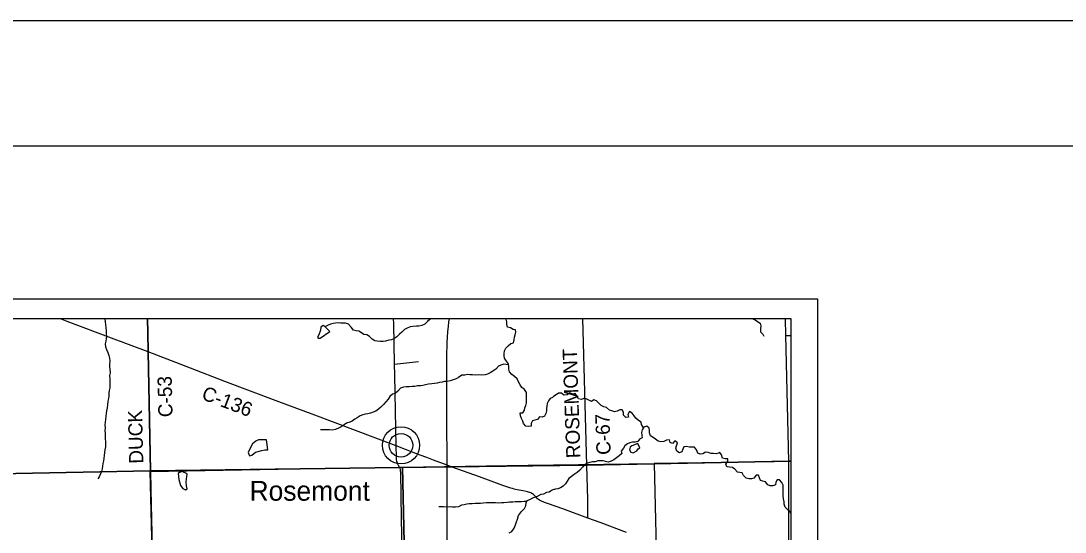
# Model space of a CAD drawing. Extents: x 0 to 34, y 0 to 22.
# Drawn here: x 6.707 to 10.885, y 19.953 to 22 of the extents above; entities that cross this region are included whole.
import ezdxf

# ---------------------------------------------------------------- set-up
doc = ezdxf.new("R2010")
doc.units = 0
for name, color, linetype in [('GM_X_Corporation', 7, 'Continuous'), ('GM_X_County_Road', 7, 'Continuous'), ('GM_X_County_Road_Text', 7, 'Continuous'), ('GM_X_Minor_Lake', 7, 'Continuous'), ('GM_X_Minor_River', 7, 'Continuous'), ('GM_X_Rail_Line', 7, 'Continuous'), ('GM_X_State_Route', 7, 'Continuous'), ('GM_X_Township_Road', 7, 'Continuous'), ('GM_X_Unincorporated', 7, 'Continuous'), ('GM_X_Unincorporated_Location', 7, 'Continuous'), ('GM_X_Unincorporated_Text', 7, 'Continuous'), ('SH_Border', 7, 'Continuous'), ('SH_Cut_Line', 7, 'Continuous'), ('SH_Data', 7, 'Continuous')]:
    doc.layers.add(name, color=color, linetype=linetype)

msp = doc.modelspace()

# ---------------------------------------------------------------- linework, layer by layer
at = {"layer": 'GM_X_Corporation'}
for points in [[(7.2136, 20.8069), (2.9895, 20.8069), (2.9895, 20.1176), (3.1549, 20.1187), (4.9925, 20.1548), (5.7004, 20.168), (6.0786, 20.1754), (7.2254, 20.198), (7.2157, 20.6753), (7.2146, 20.7526)], [(9.7895, 20.2375), (9.7895, 20.8069), (7.2136, 20.8069), (7.2146, 20.7526), (7.2157, 20.6753), (7.2254, 20.198), (8.2231, 20.2112), (8.4324, 20.2139), (8.9707, 20.221), (9.7789, 20.2374)], [(9.2406, 20.2272), (9.2644, 19.2076), (8.2571, 19.1893), (8.2335, 20.2135), (8.7368, 20.2215)], [(9.7895, 19.2182), (9.7895, 20.2353), (9.7215, 20.2341), (9.2406, 20.2272), (9.2644, 19.2076)], [(8.2335, 20.2135), (8.2571, 19.1893), (7.2437, 19.1696), (7.2401, 19.5595), (7.2243, 20.1958), (7.7364, 20.2052)]]:
    msp.add_lwpolyline(points, close=True, dxfattribs=at)
for points in [[(9.7895, 15.1275), (9.7895, 20.2375), (9.7789, 20.2374), (8.9707, 20.221), (8.4324, 20.2139), (8.2231, 20.2112), (7.2254, 20.198), (7.2266, 20.122), (7.2291, 20.0061), (7.2317, 19.8848), (7.2344, 19.7492), (7.237, 19.6097), (7.2392, 19.4543), (7.2426, 19.2998), (7.2468, 19.0896), (7.2467, 19.0557), (7.2751, 17.5764), (7.2764, 17.5202), (7.2799, 17.4174), (7.283, 17.3071), (7.2872, 17.1772)], [(7.2872, 17.1772), (7.283, 17.3071), (7.2799, 17.4174), (7.2764, 17.5202), (7.2751, 17.5764), (7.2467, 19.0557), (7.2468, 19.0896), (7.2426, 19.2998), (7.2392, 19.4543), (7.237, 19.6097), (7.2344, 19.7492), (7.2317, 19.8848), (7.2291, 20.0061), (7.2266, 20.122), (7.2254, 20.198), (6.0786, 20.1754), (5.7004, 20.168), (4.9925, 20.1548), (3.1549, 20.1187), (2.9895, 20.1176), (2.9895, 14.989)]]:
    msp.add_lwpolyline(points, dxfattribs=at)
at = {"layer": 'GM_X_County_Road'}
msp.add_line((9.7678, 20.7398), (9.7895, 20.7405), dxfattribs=at)
for points in [[(7.2159, 20.6747), (7.0699, 20.7296), (6.8916, 20.7969), (6.865, 20.8069)], [(7.2256, 20.1974), (7.2159, 20.6747), (7.2148, 20.7521), (7.2138, 20.8069)], [(8.2079, 20.2985), (8.2072, 20.3674), (8.2029, 20.5818), (8.202, 20.6251), (8.1986, 20.789), (8.1983, 20.8069)], [(8.9709, 20.2185), (8.9709, 20.2205), (8.9569, 20.7602), (8.9556, 20.8069)], [(8.2079, 20.2985), (7.8827, 20.4213), (7.7288, 20.4791), (7.5235, 20.5566), (7.3849, 20.6093), (7.2159, 20.6747)], [(8.2177, 20.2203), (8.2147, 20.2255), (8.2131, 20.2296), (8.2118, 20.2333), (8.2108, 20.2369), (8.21, 20.2424), (8.2095, 20.2475), (8.2093, 20.2532), (8.2079, 20.2985)], [(8.4121, 20.221), (8.3573, 20.2415), (8.3308, 20.2515), (8.3047, 20.2613), (8.2452, 20.2838), (8.2079, 20.2985)], [(7.2469, 19.0552), (7.247, 19.089), (7.2428, 19.2992), (7.2394, 19.4537), (7.2372, 19.6092), (7.2346, 19.7487), (7.2319, 19.8843), (7.2293, 20.0056), (7.2268, 20.1215), (7.2256, 20.1974)], [(8.2622, 18.3652), (8.2632, 18.4054), (8.2621, 18.4472), (8.2592, 18.5595), (8.2549, 18.7216), (8.2466, 19.0147), (8.2435, 19.1769), (8.2421, 19.255), (8.2402, 19.3805), (8.2379, 19.507), (8.2357, 19.6472), (8.2338, 19.785), (8.2321, 19.8769), (8.2296, 20.0073), (8.2268, 20.1925), (8.2264, 20.1978), (8.2261, 20.2017), (8.2255, 20.2048), (8.2246, 20.2076), (8.2233, 20.2106), (8.2177, 20.2203)], [(9.1303, 19.951), (9.0241, 19.991), (8.9758, 20.0091), (8.8759, 20.0468), (8.8178, 20.0667), (8.802, 20.0719), (8.7972, 20.0739), (8.7925, 20.0758), (8.7876, 20.0782), (8.7822, 20.0812), (8.7775, 20.0842), (8.7744, 20.087), (8.7697, 20.092), (8.765, 20.0968), (8.7607, 20.1009), (8.7577, 20.1036), (8.7542, 20.106), (8.7508, 20.108), (8.7472, 20.1098), (8.7432, 20.1112), (8.7386, 20.1128), (8.734, 20.1142), (8.7285, 20.1155), (8.7162, 20.1182), (8.693, 20.1224), (8.6855, 20.1241), (8.68, 20.1255), (8.6735, 20.1272), (8.6669, 20.1293), (8.6554, 20.1332), (8.6354, 20.1402), (8.5414, 20.174), (8.4326, 20.2134), (8.4121, 20.221)], [(8.9758, 20.0091), (8.9752, 20.0848), (8.9709, 20.2185)]]:
    msp.add_lwpolyline(points, dxfattribs=at)
at = {"layer": 'GM_X_Minor_Lake'}
for points in [[(7.9217, 20.7774), (7.9163, 20.7808), (7.9076, 20.7735), (7.9062, 20.7621), (7.8992, 20.7434), (7.8936, 20.7331), (7.8963, 20.7293), (7.9042, 20.7297), (7.9436, 20.7559)], [(7.9436, 20.7559), (7.9217, 20.7774)], [(7.69, 20.3221), (7.6714, 20.3231), (7.6581, 20.3222), (7.6463, 20.3168), (7.6339, 20.306), (7.623, 20.2869), (7.6159, 20.2724), (7.6221, 20.2588), (7.6312, 20.2615), (7.6452, 20.2731), (7.6714, 20.2797), (7.6824, 20.2825), (7.6945, 20.283)], [(7.6945, 20.283), (7.69, 20.3221)], [(9.1751, 20.3085), (9.1513, 20.2991), (9.1445, 20.293), (9.1427, 20.2831), (9.1474, 20.2736), (9.1566, 20.2699), (9.172, 20.2789), (9.1772, 20.2862), (9.1833, 20.2912)], [(9.1833, 20.2912), (9.1751, 20.3085)], [(7.3717, 20.1869), (7.3515, 20.1958), (7.342, 20.1919), (7.3367, 20.1873), (7.3389, 20.1642), (7.3455, 20.1403), (7.3552, 20.1282), (7.3655, 20.1226), (7.3727, 20.1264), (7.3699, 20.1382), (7.3682, 20.1538)], [(7.3682, 20.1538), (7.3717, 20.1869)]]:
    msp.add_lwpolyline(points, dxfattribs=at)
at = {"layer": 'GM_X_Minor_River'}
for points in [[(7.0432, 20.8069), (7.0437, 20.7951), (7.0453, 20.7837), (7.0473, 20.7715), (7.0482, 20.7605), (7.0487, 20.7483), (7.0488, 20.7377), (7.0477, 20.7282), (7.0463, 20.7179), (7.0437, 20.7065), (7.0454, 20.6955), (7.0493, 20.6837), (7.0547, 20.6724), (7.0582, 20.6602), (7.0617, 20.6489), (7.0622, 20.6386), (7.0612, 20.6249), (7.0617, 20.6154), (7.0633, 20.6055), (7.0638, 20.5915), (7.0616, 20.5804), (7.0621, 20.5668), (7.0626, 20.5519), (7.0623, 20.5409), (7.0624, 20.5306), (7.0603, 20.52), (7.0592, 20.5105), (7.0593, 20.4983), (7.0571, 20.488), (7.0553, 20.477), (7.0535, 20.4633), (7.0525, 20.4504), (7.0492, 20.4386), (7.0478, 20.4279), (7.0467, 20.4172), (7.0457, 20.4043), (7.0439, 20.3933), (7.0432, 20.3823), (7.0441, 20.3705), (7.0423, 20.3598), (7.0436, 20.3477), (7.044, 20.3363), (7.0437, 20.3264), (7.045, 20.3165), (7.0455, 20.3066), (7.0448, 20.2948), (7.043, 20.2819), (7.0416, 20.2709), (7.0402, 20.261), (7.0388, 20.248), (7.0369, 20.2381), (7.0348, 20.2275), (7.0337, 20.2168), (7.0315, 20.2066), (7.029, 20.1963), (7.026, 20.1864), (7.0204, 20.1742), (7.0148, 20.1669)], [(8.3455, 20.8069), (8.344, 20.8051), (8.3342, 20.7966), (8.3236, 20.7859), (8.3111, 20.7801), (8.2997, 20.7781), (8.2895, 20.7773), (8.2754, 20.7768), (8.2644, 20.7744), (8.2526, 20.7701), (8.242, 20.7644), (8.2315, 20.7533), (8.2217, 20.7452), (8.2111, 20.7345), (8.199, 20.7264), (8.1892, 20.7233), (8.1797, 20.7213), (8.1664, 20.7178), (8.1565, 20.7158), (8.1447, 20.7164), (8.1326, 20.7179), (8.1227, 20.7186), (8.1119, 20.7253), (8.1016, 20.7359), (8.0912, 20.7434), (8.0794, 20.7444), (8.0699, 20.7512), (8.0584, 20.7576), (8.0485, 20.759), (8.0371, 20.7623), (8.0282, 20.7741), (8.0171, 20.7857), (8.0056, 20.7902), (7.9961, 20.7894), (7.9866, 20.7901), (7.9763, 20.7904), (7.9657, 20.7891), (7.9558, 20.7883), (7.9456, 20.7852), (7.9357, 20.7813), (7.9259, 20.7767), (7.9246, 20.7745)], [(8.8341, 20.492), (8.8242, 20.4885), (8.8178, 20.4786), (8.813, 20.4675), (8.8119, 20.458), (8.8101, 20.4485), (8.8098, 20.4382), (8.8073, 20.4275), (8.802, 20.4176), (8.7922, 20.413), (8.7819, 20.4148), (8.7736, 20.4045), (8.7638, 20.4017), (8.7539, 20.3982), (8.7487, 20.3875), (8.748, 20.3777), (8.7374, 20.3757), (8.7267, 20.3779), (8.7175, 20.3877), (8.7159, 20.3972), (8.7104, 20.4085), (8.7054, 20.4187), (8.7049, 20.4305), (8.7148, 20.4306), (8.7219, 20.4409), (8.7238, 20.4508), (8.7275, 20.4607), (8.7304, 20.4703), (8.7302, 20.49), (8.7294, 20.501), (8.7297, 20.5121), (8.7223, 20.5238), (8.7116, 20.5321), (8.7047, 20.5434), (8.6977, 20.5551), (8.6927, 20.5665), (8.6823, 20.5763), (8.6716, 20.5838), (8.6624, 20.5944), (8.6596, 20.605), (8.6599, 20.6153), (8.6575, 20.6274), (8.6498, 20.6376), (8.6421, 20.649), (8.6405, 20.6584), (8.64, 20.6683), (8.6414, 20.679), (8.647, 20.6893), (8.6565, 20.6989), (8.6678, 20.7081), (8.678, 20.7112), (8.6802, 20.7226), (8.682, 20.7333), (8.6842, 20.7432), (8.6879, 20.7531), (8.6859, 20.7626), (8.6764, 20.7648), (8.6657, 20.7715), (8.6539, 20.7741), (8.6519, 20.7851), (8.6506, 20.7957), (8.6483, 20.8052), (8.6452, 20.8069)], [(9.6353, 20.8069), (9.6443, 20.8025), (9.6542, 20.7962), (9.6649, 20.7894), (9.6681, 20.7788), (9.6667, 20.7674), (9.6665, 20.7556), (9.6757, 20.7459), (9.68, 20.7383)], [(8.6583, 20.623), (8.6392, 20.6257), (8.6279, 20.6219), (8.618, 20.618), (8.6071, 20.6061), (8.5954, 20.5973), (8.5848, 20.5903), (8.5738, 20.5849), (8.5639, 20.583), (8.5503, 20.5817), (8.5377, 20.5824), (8.5271, 20.5811), (8.5134, 20.5829), (8.5035, 20.5829), (8.4936, 20.5839), (8.4826, 20.5819), (8.4715, 20.5811), (8.4579, 20.5726), (8.4481, 20.5672), (8.436, 20.5626), (8.4242, 20.5587), (8.412, 20.5567), (8.4014, 20.5566), (8.3919, 20.5531), (8.3817, 20.5515), (8.3722, 20.5499), (8.3619, 20.5483), (8.3505, 20.5474), (8.3384, 20.5454), (8.3262, 20.5427), (8.3152, 20.5407), (8.3057, 20.5391), (8.2939, 20.5386), (8.2825, 20.5366), (8.2726, 20.5362), (8.2605, 20.5345), (8.2479, 20.5348), (8.2373, 20.5328), (8.2252, 20.5289), (8.215, 20.5178), (8.2044, 20.5075), (8.1942, 20.5059), (8.1829, 20.4955), (8.1765, 20.486), (8.1667, 20.4741), (8.1573, 20.4634), (8.1471, 20.4538), (8.1373, 20.445), (8.1271, 20.4373), (8.1169, 20.4338), (8.1051, 20.4299), (8.0956, 20.4268), (8.0839, 20.4248), (8.0744, 20.4225), (8.0645, 20.419), (8.0524, 20.4105), (8.0426, 20.4051), (8.0324, 20.3978), (8.0225, 20.3928), (8.01, 20.3889), (7.9998, 20.3823), (7.9881, 20.3742), (7.9756, 20.3677), (7.9642, 20.3642), (7.9528, 20.3618), (7.9422, 20.3625), (7.9201, 20.3623), (7.9098, 20.363), (7.906, 20.363)], [(9.1981, 20.3705), (9.1904, 20.384), (9.1884, 20.3938), (9.178, 20.3998), (9.1677, 20.4091), (9.1607, 20.4193), (9.1522, 20.4298), (9.1419, 20.4354), (9.1356, 20.4243), (9.138, 20.4137), (9.1274, 20.4121), (9.1185, 20.4218), (9.1176, 20.4328), (9.1126, 20.443), (9.1031, 20.4433), (9.0929, 20.4375), (9.0819, 20.4351), (9.072, 20.4391), (9.0625, 20.4417), (9.0502, 20.4518), (9.0388, 20.4547), (9.0292, 20.4606), (9.0192, 20.4692), (9.0096, 20.4782), (8.9997, 20.4823), (8.9899, 20.4761), (8.9792, 20.4809), (8.9693, 20.4873), (8.9598, 20.4879), (8.9496, 20.4844), (8.9374, 20.4869), (8.9319, 20.499), (8.9246, 20.5087), (8.9148, 20.5048), (8.9037, 20.5104), (8.8928, 20.5027), (8.8799, 20.5017), (8.8695, 20.51), (8.8585, 20.5098), (8.8484, 20.5021), (8.8382, 20.4955), (8.8341, 20.492)], [(9.7895, 20.028), (9.7852, 20.0341), (9.7752, 20.0419), (9.7656, 20.0532), (9.7616, 20.065), (9.7611, 20.0745), (9.7583, 20.0866), (9.757, 20.0983), (9.7568, 20.1188), (9.757, 20.1306), (9.7576, 20.1409), (9.7518, 20.1522), (9.7429, 20.162), (9.733, 20.163), (9.7279, 20.1527), (9.7265, 20.142), (9.7151, 20.1385), (9.7049, 20.1387), (9.6953, 20.1428), (9.6865, 20.1545), (9.6762, 20.157), (9.6663, 20.1592), (9.6616, 20.1709), (9.6588, 20.1807), (9.6493, 20.1806), (9.64, 20.1695), (9.6297, 20.1667), (9.6202, 20.1666), (9.6092, 20.1691), (9.5988, 20.1792), (9.5934, 20.1906), (9.5839, 20.192), (9.574, 20.1937), (9.5636, 20.2054), (9.5536, 20.2113), (9.5426, 20.2127), (9.5319, 20.2145), (9.5273, 20.2247), (9.5355, 20.2366), (9.535, 20.2461), (9.5255, 20.2463), (9.514, 20.2496), (9.5108, 20.2621), (9.5039, 20.2719), (9.4899, 20.2672), (9.4785, 20.2678), (9.469, 20.2673), (9.4568, 20.2721), (9.4462, 20.2727), (9.4356, 20.2665), (9.425, 20.2652), (9.4155, 20.2686), (9.4107, 20.2829), (9.4026, 20.2931), (9.3924, 20.293), (9.3817, 20.2932), (9.3703, 20.2954), (9.3601, 20.2948), (9.356, 20.2853), (9.352, 20.275), (9.3422, 20.2711), (9.3315, 20.277), (9.3275, 20.2895), (9.3304, 20.299), (9.3341, 20.3105), (9.3241, 20.318), (9.3147, 20.3083), (9.3048, 20.312), (9.3017, 20.3226), (9.2899, 20.3213), (9.2793, 20.3159), (9.268, 20.3146), (9.2566, 20.3171), (9.2466, 20.325), (9.2366, 20.3313), (9.2267, 20.338), (9.2227, 20.3502), (9.2218, 20.3596), (9.2213, 20.3695), (9.211, 20.3777), (9.2, 20.3731), (9.1922, 20.3627), (9.1901, 20.352), (9.1917, 20.3407), (9.1922, 20.3312), (9.1821, 20.3253), (9.1757, 20.3154), (9.1644, 20.3126), (9.1537, 20.3128), (9.1439, 20.3112), (9.1337, 20.3061), (9.1236, 20.2988), (9.118, 20.2892), (9.109, 20.2777), (9.1114, 20.2675), (9.1006, 20.2582), (9.0896, 20.2509)], [(9.0896, 20.2509), (9.0795, 20.242), (9.0686, 20.2373), (9.0572, 20.2338), (9.0466, 20.2355), (9.0363, 20.2381), (9.0249, 20.2387), (9.015, 20.2382), (9.0052, 20.2347), (8.9942, 20.2345), (8.9832, 20.2317), (8.9734, 20.2297), (8.9628, 20.2235), (8.9535, 20.2135), (8.943, 20.2012), (8.9325, 20.1912), (8.9208, 20.1842), (8.9103, 20.1761), (8.899, 20.168), (8.892, 20.1569), (8.8864, 20.1462), (8.8763, 20.1366), (8.8657, 20.1308), (8.8559, 20.1261), (8.8446, 20.1245)], [(8.6606, 19.9501), (8.6708, 19.9559), (8.6802, 19.9693), (8.6854, 19.9823), (8.6899, 19.9937), (8.694, 20.0055), (8.6984, 20.0196), (8.7104, 20.0353), (8.7221, 20.0472), (8.7277, 20.059), (8.7291, 20.0704), (8.7332, 20.0803), (8.7438, 20.0842), (8.7556, 20.0908), (8.7669, 20.0946), (8.7772, 20.0989), (8.7881, 20.1047), (8.7992, 20.1067), (8.8109, 20.1129), (8.8204, 20.1148), (8.8306, 20.1206), (8.8412, 20.1245), (8.8446, 20.1245)], [(8.7313, 20.0756), (8.72, 20.0756), (8.7101, 20.0744), (8.6975, 20.0747), (8.685, 20.0742), (8.6747, 20.0734), (8.6618, 20.0729), (8.6523, 20.0721), (8.6394, 20.0708), (8.6295, 20.0707), (8.6188, 20.0691), (8.6059, 20.0702), (8.5705, 20.0699), (8.5565, 20.069), (8.5462, 20.0678), (8.5363, 20.0681), (8.5241, 20.068), (8.5127, 20.066), (8.5002, 20.0659), (8.4907, 20.0647), (8.4804, 20.0627), (8.4698, 20.0611), (8.4581, 20.0546), (8.4452, 20.0526), (8.4341, 20.0536), (8.4239, 20.0543), (8.4102, 20.053), (8.3984, 20.0541), (8.3881, 20.0544), (8.3786, 20.0543)]]:
    msp.add_lwpolyline(points, dxfattribs=at)
at = {"layer": 'GM_X_Rail_Line'}
msp.add_lwpolyline([(8.4128, 19.913), (8.4124, 20.2199), (8.4118, 20.4151), (8.4118, 20.4876), (8.4116, 20.5917), (8.4118, 20.6468), (8.4113, 20.6707), (8.4124, 20.698), (8.413, 20.7145), (8.4139, 20.7325), (8.4156, 20.7561), (8.4176, 20.7758), (8.4198, 20.795), (8.4215, 20.8069)], dxfattribs=at)
at = {"layer": 'GM_X_State_Route'}
msp.add_line((9.7678, 20.7398), (9.7668, 20.8069), dxfattribs=at)
msp.add_lwpolyline([(9.7895, 18.7757), (9.7895, 18.7775), (9.7813, 19.7048), (9.7799, 19.9155), (9.7791, 20.2369), (9.7678, 20.7398)], dxfattribs=at)
at = {"layer": 'GM_X_Township_Road'}
msp.add_line((8.202, 20.6251), (8.2972, 20.6356), dxfattribs=at)
at = {"layer": 'GM_X_Unincorporated'}
for radius in [0.0744, 0.0472]:
    msp.add_circle((8.2278, 20.3007), radius, dxfattribs=at)
at = {"layer": 'GM_X_Unincorporated_Location'}
msp.add_line((8.2278, 20.3007), (8.2278, 20.3007), dxfattribs=at)
at = {"layer": 'SH_Border'}
msp.add_lwpolyline([(1.5, 21.5), (33.5, 21.5), (33.5, 0.5), (1.5, 0.5)], close=True, dxfattribs=at)
at = {"layer": 'SH_Cut_Line'}
msp.add_lwpolyline([(0, 0), (34, 0), (34, 22), (0, 22)], close=True, dxfattribs=at)
at = {"layer": 'SH_Data'}
for p, q in [((2.8945, 20.8873), (9.8945, 20.8873)), ((9.8945, 20.8873), (9.8945, 13.8873))]:
    msp.add_line(p, q, dxfattribs=at)

# ---------------------------------------------------------------- texts
at = {"layer": 'GM_X_County_Road_Text'}
for s, rotation, p in [('ROSEMONT', 92.0006, (8.9462, 20.2499)), ('C-53', 91.3713, (7.3139, 20.4139)), ('C-136', 339.2185, (7.426, 20.4867)), ('DUCK', 91.4565, (7.197, 20.2276)), ('C-67', 92.0565, (9.0672, 20.2634))]:
    msp.add_text(s, height=0.05682, rotation=rotation, dxfattribs=at).set_placement(p)
at = {"layer": 'GM_X_Unincorporated_Text'}
msp.add_text('Rosemont', height=0.07898, rotation=0, dxfattribs=at).set_placement((7.6218, 20.0789))

doc.saveas('drawing.dxf')
